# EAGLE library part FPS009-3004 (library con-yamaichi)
SD Card and MMC Reader (Manual Insertion) Source: http://www.yamaichi.de/pdf/c_fps009_3000.pdf
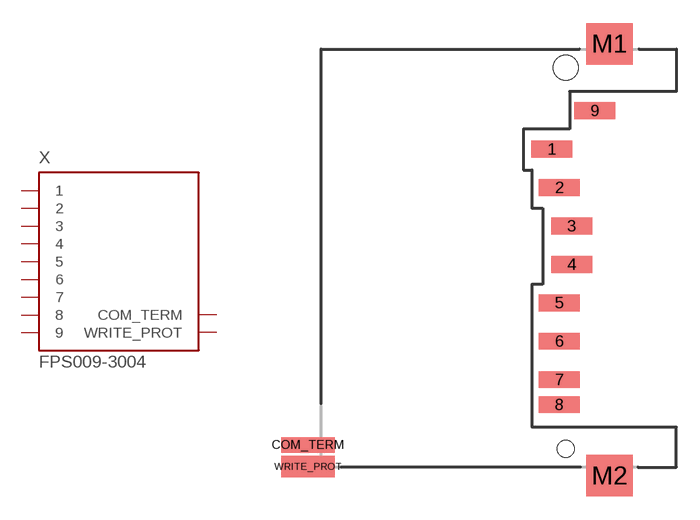
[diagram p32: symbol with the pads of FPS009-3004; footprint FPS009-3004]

Designator prefix X

## FPS009-3004 (OC_FARNELL: unknown; OC_NEWARK: unknown)  [FPS009-3004]
1  1  in
2  2  in
3  3  in
4  4  in
5  5  in
6  6  in
7  7  in
8  8  in
9  9  in
COM_TERM  COM_TERM  in
WRITE_PROT  WRITE_PROT  in

## Footprint FPS009-3004 (pad centres in mm)
SD Card and MMC Reader (Manual Insertion) Source: http://www.yamaichi.de/pdf/c_fps009_3000.pdf
smd 2.65 x 1.1: 1 -0.915,-5.3; 2 -0.415,-7.8; 3 0.385,-10.3; 4 0.385,-12.8; 5 -0.415,-15.3; 6 -0.415,-17.8; 7 -0.415,-20.3; 8 -0.415,-21.925; 9 1.885,-2.8
smd 3.5 x 1: COM_TERM -16.75,-24.55
smd 3 x 2.7: M1 2.85,1.55; M2 2.85,-26.55
smd 3.5 x 1.4: WRITE_PROT -16.75,-25.95
hole 1.6 at 0,0
hole 1.1 at 0,-24.8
